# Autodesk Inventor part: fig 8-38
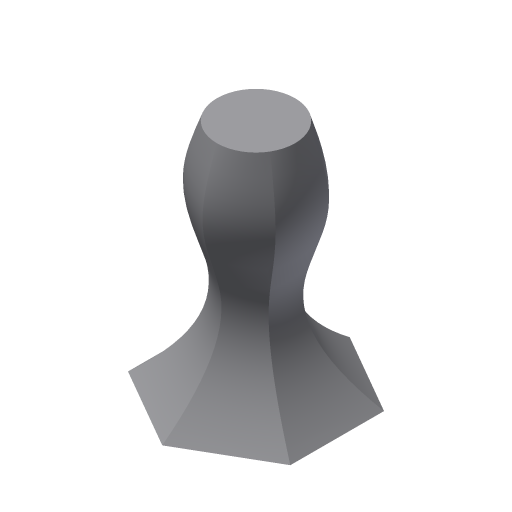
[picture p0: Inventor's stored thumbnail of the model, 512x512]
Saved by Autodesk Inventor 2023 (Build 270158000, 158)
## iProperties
Created: 2007-05
Part Number: fig 8-38
Document SubType Name: Modeling
Designer: Administrator
Density: 1 g/cm^3
Material: Generic
Appearance: Default
Author: Administrator
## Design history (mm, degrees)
sketch "Sketch1"
  geometry: L1 (0, 30)-(25.981, 15); L2 (25.981, 15)-(25.981, -15); L3 (25.981, -15)-(0, -30); L4 (0, -30)-(-25.981, -15); L5 (-25.981, -15)-(-25.981, 15); L6 (-25.981, 15)-(0, 30); 2 further points
  constraints: 12 end point, 1 coincident, 1 vertical, 14 other
workplane "Work Plane1"
sketch "Sketch2"
  geometry: C1 r 12.5 at (0, 0)
  constraints: 1 centre point, 1 other
sketch "Sketch3"
  geometry: L1 (0, 0)-(0, 75)
  constraints: 2 end point, 1 vertical, 1 other
loft "Loft1" sketch "Sketch2", "Sketch3" dims "d5" = 0, "d6" = 90 deg, "d7" = 0, "d8" = 90 deg, "d9" = 0, "d10" = 90 deg, "d11" = 0, "d12" = 0, "d13" = 233.82686, "d14" = 10, "d15" = 75, "d16" = 10, "d17" = 49.08739, "d18" = 10, "d19" = 32.19705, "d20" = 4.29294, "d21" = 35, "d22" = 2.53907, "d23" = 56.85952, "d24" = 7.58127, "d25" = 85, "d26" = 10.45619
body "Solid1"
other parameters: "d1" = 75
